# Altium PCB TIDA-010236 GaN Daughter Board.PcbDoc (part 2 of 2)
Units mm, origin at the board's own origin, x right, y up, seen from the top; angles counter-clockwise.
Board outline 68 x 45 mm, 4 copper layers (Top Layer, Signal Layer 1, Signal Layer 2, Bottom Layer), stack 1.57 mm thick; 74 components, 38 nets, 269 pads, 167 vias.
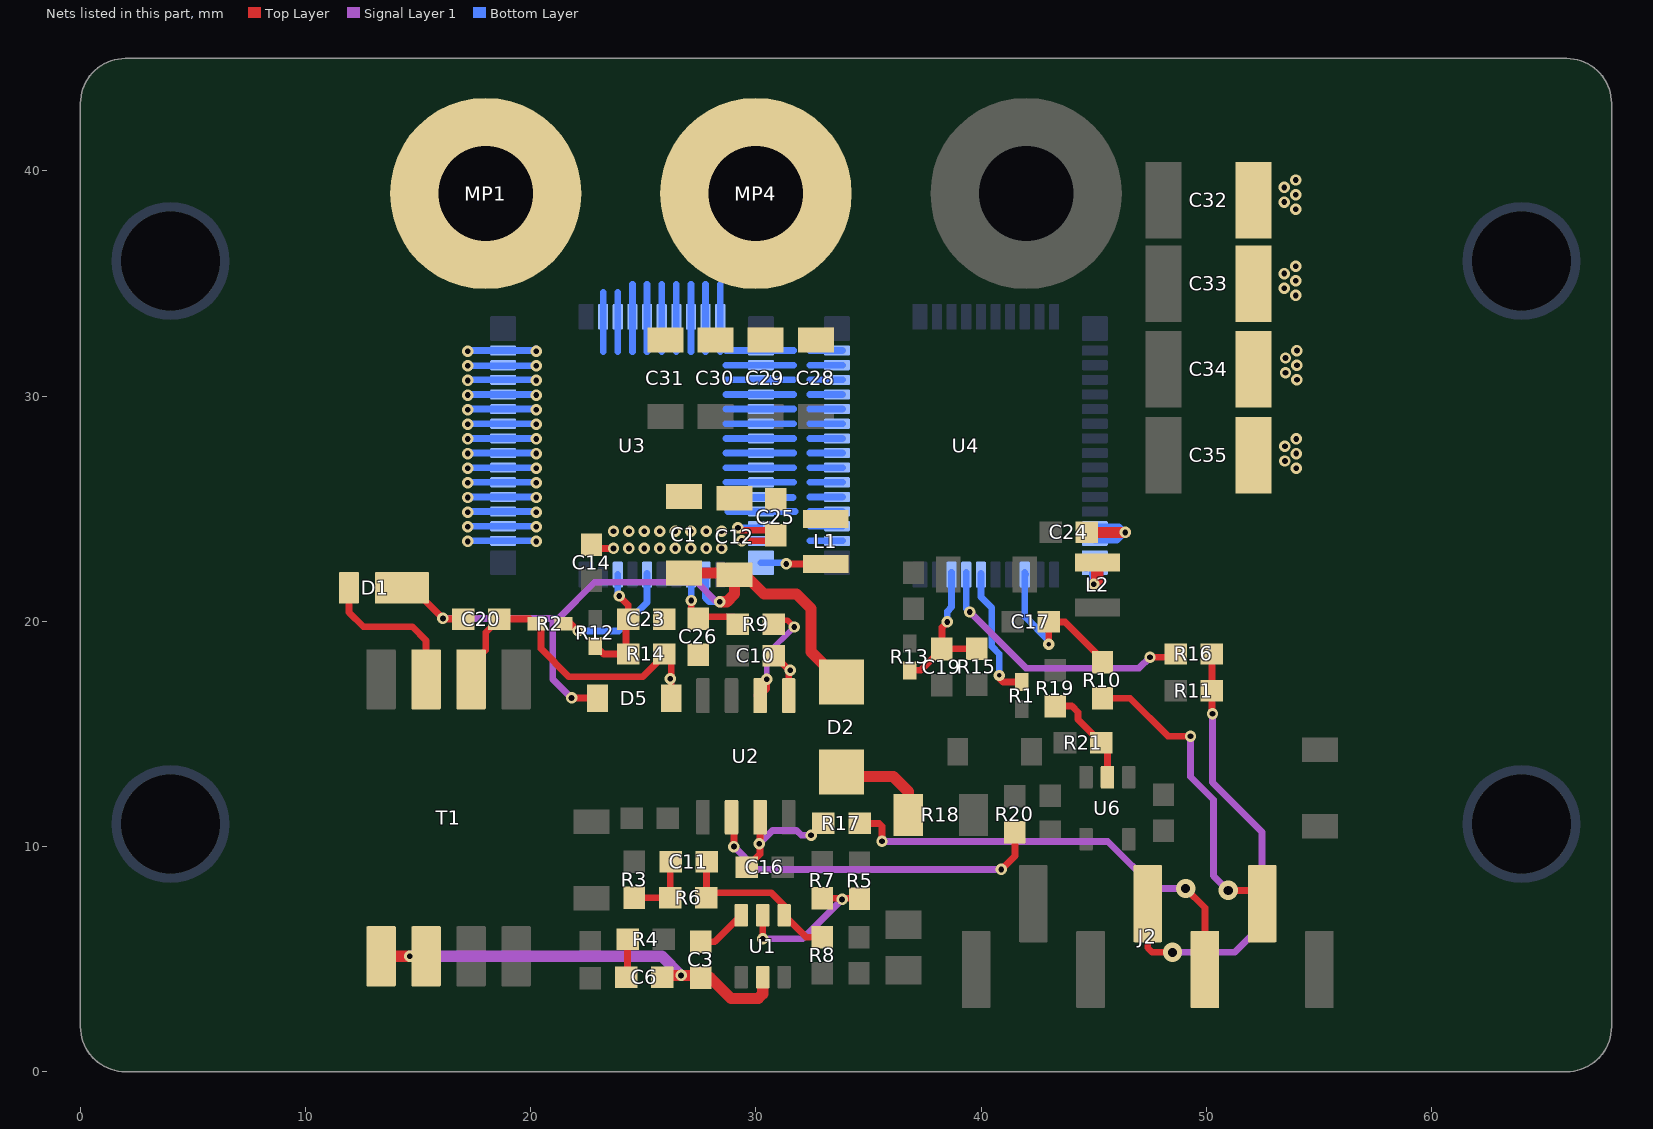
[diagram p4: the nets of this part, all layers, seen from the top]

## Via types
v1: diameter 0.508, hole 0.254, Top Layer to Bottom Layer, tented both sides, 150 vias
v2: diameter 0.5, hole 0.2, Top Layer to Bottom Layer, 12 vias
v3: diameter 0.864, hole 0.406, Top Layer to Bottom Layer, 5 vias

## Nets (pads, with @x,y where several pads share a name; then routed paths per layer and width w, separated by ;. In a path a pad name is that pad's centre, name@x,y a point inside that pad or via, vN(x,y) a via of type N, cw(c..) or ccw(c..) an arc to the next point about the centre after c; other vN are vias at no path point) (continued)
HV_BUS: C28.1 C29.1 C30.1 C31.1 C32.1 C33.1 C34.1 C35.1 MP1.1 U3.2 U3.3 U3.4 U3.5 U3.6 U3.7 U3.8 U3.9 U3.10 U3.11 U3.12 U3.13 U3.14 U3.15 | length 42.1
  Bottom Layer w0.3: v1(17.2,32) 17.225,32.025 U3.15@18.775,32.025 v1@20.225,32.025 ; v1@17.225,23.575 U3.2@18.775,23.575 v1@20.225,23.575 ; v1@17.225,24.225 U3.3@18.775,24.225 v1@20.225,24.225 ; v1@17.225,24.875 U3.4@18.775,24.875 v1@20.225,24.875 ; v1@17.225,25.525 U3.5@18.775,25.525 v1@20.225,25.525 ; v1@17.225,26.175 U3.6@18.775,26.175 v1@20.225,26.175 ; v1@17.225,26.825 U3.7@18.775,26.825 v1@20.225,26.825 ; v1@17.225,27.475 U3.8@18.775,27.475 v1@20.225,27.475 ; v1@17.225,28.125 U3.9@18.775,28.125 v1@20.225,28.125 ; v1@17.225,28.775 U3.10@18.775,28.775 v1@20.225,28.775 ; v1@17.225,29.425 U3.11@18.775,29.425 v1@20.225,29.425 ; v1@17.225,30.075 U3.12@18.775,30.075 v1@20.225,30.075 ; v1@17.225,30.725 U3.13@18.775,30.725 v1@20.225,30.725 ; v1@17.225,31.35 18.775,31.35 v1@20.225,31.35
  Bottom Layer w0.45: v1@20.225,32.025 v1(20.25,32)
  other v1: 17.2,23.55 20.25,23.55 17.2,24.2 20.25,24.2 17.2,24.85 20.25,24.85 17.2,25.5 20.25,25.5 17.2,26.15 20.25,26.15 17.2,26.8 20.25,26.8 54,26.8 53.492,27.12 17.2,27.45 20.25,27.45 54,27.45 53.492,27.77 17.2,28.1 20.25,28.1 54,28.1 17.2,28.75 20.25,28.75 17.2,29.4 20.25,29.4 17.2,30.05 20.25,30.05 17.2,30.7 20.25,30.7 54.025,30.725 53.517,31.045 17.2,31.35 20.25,31.35 54.025,31.375 53.517,31.695 54.025,32.025 53.975,34.475 53.467,34.795 53.975,35.125 53.467,35.445 53.975,35.775 53.975,38.3 53.467,38.62 53.975,38.95 53.467,39.27 53.975,39.6
ISO-15V: C1.1 C12.1 C20.1 D1.1 D2.1 D5.1 U3.44 | length 35.3
  Top Layer w0.3: D1.1@14.45,21.49 14.741,21.49 v1(16.1,20.131) 16.131,20.1 C20.1@17,20.1 ; v1(21.814,16.6) 22.915,16.6 22.801,16.714 22.812,16.725 D5.1@22.962,16.575 ; C1.1@26.8,22.15 C1.1@26.929,22.15
  Top Layer w0.5: C1.1@26.929,22.15 28.967,22.15 C12.1@29.05,22.067 ; v1(28.399,20.867) 28.705,20.867 29.05,21.212 C12.1@29.05,22.067 ; D2.1@33.8,17.3 32.45,18.65 32.45,20.569 31.804,21.216 30.366,21.216 29.515,22.067 C12.1@29.05,22.067
  Signal Layer 1 w0.3: v1(16.1,20.131) 20.975,20.131 ; v1(21.814,16.6) 20.975,17.439 20.975,20.131 ; v1(28.399,20.867) 28.258,20.867 27.389,21.736 22.836,21.736 21.231,20.131 20.975,20.131
  Bottom Layer w0.3: U3.44@27.765,22.075 27.765,21.044 27.942,20.867 v1(28.399,20.867)
NetC3_1: C3.1 C6.2 T1.1 T1.2 U1.2 | length 20.1
  Top Layer w0.5: T1.1@13.35,5.125 v1(14.625,5.125) T1.2@15.35,5.125 ; C6.2@25.85,4.2 25.925,4.275 v1(26.675,4.275) C3.1@27.55,4.275 ; C3.1@27.55,4.175 27.968,4.175 28.893,3.25 30.1,3.25 30.3,3.45 U1.2@30.3,4.2
  Signal Layer 1 w0.5: v1(14.625,5.125) 25.825,5.125 v1(26.675,4.275)
NetC3_2: C3.2 U1.6 | length 2.3
  Top Layer w0.3: C3.2@27.55,5.775 28.175,5.775 U1.6@29.35,6.95
NetC6_1: C6.1 R4.1 | length 1.7
  Top Layer w0.3: C6.1@24.25,4.2 24.3,4.25 R4.1@24.3,5.875
NetC11_1: C11.1 R3.1 R6.2 | length 3.2
  Top Layer w0.3: R3.1@24.594,7.725 R6.2@26.2,7.725 26.2,9.298 C11.1@26.225,9.323
NetC11_2: C11.2 R6.1 R8.2 U1.4 | length 7.9
  Top Layer w0.3: C11.2@27.825,9.323 27.8,9.298 R6.1@27.8,7.725 28.025,7.95 30.675,7.95 31.25,7.375 U1.4@31.25,6.95 32.225,5.975 R8.2@32.94,5.975
NetC16_1: C16.1 R17.2 U2.3 | length 5.9
  Top Layer w0.3: C16.1@29.6,9.075 30.185,9.66 U2.3@30.185,11.3 ; v1(32.45,10.5) 32.475,10.5 R17.2@33,11.025
  Signal Layer 1 w0.3: v1(30.15,10.125) 30.741,10.716 31.8,10.716 32.016,10.5 v1(32.45,10.5)
NetC17_1: C17.1 R10.1 U4.45 | length 8.2
  Top Layer w0.3: v2@43.064,19.041 v2(43,18.978) C17.1@43,19.974 43.735,19.974 45.484,18.225 R10.1@45.689,18.225
  Bottom Layer w0.3: U4.45@41.94,22.075 41.94,20.213 43,19.153 v2(43,18.978) ; U4.45@41.94,22.183 41.94,22.125 41.971,22.094 U4.45@41.971,22.075
NetC19_1: C19.1 R13.2 R15.2 U4.50 | length 7.2
  Top Layer w0.3: R13.2@36.825,17.825 37.313,17.825 C19.1@38.26,18.772 ; R13.2@36.85,17.84 R13.2@37.065,17.84 ; v1(38.5,19.974) 38.26,19.734 C19.1@38.26,18.772 ; R15.2@39.799,18.785 38.273,18.785 C19.1@38.26,18.772
  Bottom Layer w0.3: v1(38.5,19.974) 38.5,20.445 38.69,20.635 38.69,22.125 U4.50@38.69,22.183
NetC23_1: C23.1 R12.2 R14.2 U3.50 | length 5.6
  Top Layer w0.3: R12.2@22.875,18.9 23.225,18.55 R14.2@24.325,18.55 ; v1(23.925,21.125) 24.325,20.725 C23.1@24.325,20.1 24.225,20 24.225,18.725 R14.2@24.3,18.65 ; C23.1@24.001,19.926 C23.1@24.225,20.126
  Bottom Layer w0.3: U3.50@23.865,22.075 23.865,21.135 23.875,21.125 v1(23.925,21.125)
NetC24_1: C24.1 U4.40 U4.41 | length 5.2
  Top Layer w0.254: C24.1@44.7,23.95 C24.1@45.033,24.283
  Top Layer w0.5: C24.1@44.7,23.95 v1(46.403,23.95)
  Bottom Layer w0.254: U4.40@45,24.283 U4.40@45.058,24.225 ; U4.41@45.05,23.575 46.028,23.575 v1(46.403,23.95) 46.128,24.225 U4.40@45.058,24.225 ; U4.40@45.05,24.225 U4.40@45.058,24.225
NetC25_1: C25.1 U3.40 U3.41 | length 5.3
  Top Layer w0.3: v1(29.2,24.159) 29.309,24.05 30.608,24.05 30.885,23.773 30.638,23.525 30.588,23.575 v1(29.375,23.575)
  Bottom Layer w0.3: v1(29.2,24.159) 30.109,24.159 U3.40@30.175,24.225 ; v1(29.375,23.575) U3.41@30.175,23.575
NetC26_1: C26.1 R9.1 U3.45 | length 3.4
  Top Layer w0.3: v1(27.125,20.925) 27.125,20.441 27.425,20.141 C26.1@27.46,20.176 ; C26.1@27.65,20.209 R9.1@28.984,20.209
  Bottom Layer w0.3: U3.45@27.115,22.075 27.125,22.065 v1(27.125,20.925)
NetD1_2: D1.2 T1.7 | length 6.8
  Top Layer w0.3: D1.2@11.925,21.49 11.925,20.4 12.562,19.763 14.737,19.763 15.35,19.15 T1.7@15.35,17.425
NetD2_2: D2.2 R18.2 | length 4.4
  Top Layer w0.5: D2.2@33.8,13.3 33.986,13.114 36.1,13.114 36.765,12.448 R18.2@36.765,11.4
NetL1_2: L1.2 U3.42 | length 2.9
  Top Layer w0.3: v1(31.35,22.55) L1.2@33.1,22.55
  Bottom Layer w0.3: U3.42@30.225,22.6 31.3,22.6 v1(31.35,22.55)
NetL2_2: L2.2 U4.42 | length 3.9
  Top Layer w0.254: v1(45.004,21.647) 45.004,22.286 44.925,22.365 L2.2@45.175,22.615
  Top Layer w0.5: v1(45.004,21.647) 45.175,21.818 L2.2@45.175,22.615
  Bottom Layer w0.254: U4.42@44.65,22.308 U4.42@45,22.658 ; v1(45.004,21.647) 45.004,21.954
  Bottom Layer w0.5: v1(45.004,21.647) 45.05,21.693 U4.42@45.05,22.6
NetR1_2: R1.2 U4.48 | length 6.1
  Top Layer w0.3: v2(40.807,17.6) 40.807,17.469 40.976,17.301 R1.2@41.8,17.301
  Bottom Layer w0.3: U4.48@39.99,22.125 U4.48@39.99,22.075 39.99,21.086 40.476,20.6 40.476,18.885 40.807,18.554 v2(40.807,17.6)
NetR2_2: R2.2 U3.48 | length 5.8
  Top Layer w0.3: R2.2@21.35,19.9 21.775,19.9 v1(22.1,19.575)
  Bottom Layer w0.3: v1(22.1,19.575) 23.904,19.575 25.165,20.836 U3.48@25.165,22.125
NetR5_1: R5.1 R7.2 U1.5 | length 7
  Top Layer w0.3: v1(30.3,5.909) U1.5@30.3,6.95 ; R7.2@32.94,7.7 34.575,7.7 R5.1@34.6,7.675
  Signal Layer 1 w0.3: v1(30.3,5.909) 32.084,5.909 v1(33.825,7.65)
NetR16_2: R16.2 U4.49 | length 13.1
  Top Layer w0.3: v1(47.5,18.4) 48.5,18.4 R16.2@48.65,18.55
  Signal Layer 1 w0.3: v1(39.5,20.415) 41.995,17.92 47.02,17.92 v1(47.5,18.4)
  Bottom Layer w0.3: 39.34,21.26 U4.49@39.34,22.183 ; U4.49@39.34,22.075 39.34,20.575 v1(39.5,20.415)
NetR19_2: R19.2 R21.2 U6.2 | length 4.6
  Top Layer w0.3: R19.2@43.246,16.434 R19.2@43.293,16.434 ; R19.2@43.293,16.235 44.028,16.235 44.3,15.963 44.3,15.639 R21.2@45.326,14.613 45.611,14.328 U6.2@45.611,13.075
NetR20_1: R20.1 U2.2 | length 15.6
  Top Layer w0.3: U2.2@28.915,11.3 28.82,11.205 29.021,11.003 v1(29.021,9.999) ; v1(40.9,8.984) 41.5,9.584 R20.1@41.5,10.628
  Signal Layer 1 w0.3: v1(29.021,9.999) 30.036,8.984 v1(40.9,8.984)
PWM_H: J2.3 R17.1 | length 20
  Top Layer w0.3: R17.1@34.6,11.025 35.475,11.025 35.6,10.9 v1(35.6,10.228) ; v3(49.084,8.135) 49.94,7.279 J2.3@49.94,4.54
  Signal Layer 1 w0.3: v1(35.6,10.228) 45.623,10.228 47.715,8.135 v3(49.084,8.135)
PWM_HS: R9.2 U2.6 | length 4.8
  Top Layer w0.254: R9.2@30.825,20.05 31.4,20.05 v1(31.7,19.75)
  Top Layer w0.3: U2.6@30.05,16.7 U2.6@30.185,16.7 30.475,16.99 v1(30.475,17.425)
  Signal Layer 1 w0.254: v1(30.475,17.425) 30.475,18.525 v1(31.7,19.75)
PWM_L: J2.2 R10.2 | length 13.9
  Top Layer w0.3: R10.2@45.389,16.585 46.615,16.585 48.3,14.9 v1(49.3,14.9) ; R10.2@45.457,16.981 R10.2@45.623,16.816 ; v3(50.974,8.049) 52.339,8.049 J2.2@52.46,8.17
  Signal Layer 1 w0.3: v1(49.3,14.9) 49.3,13.1 50.324,12.076 50.324,8.699 v3(50.974,8.049)
SW: C1.2 C10.2 C12.2 C14.1 C20.2 C23.2 C25.2 C26.2 D5.2 L1.1 MP4.1 R2.1 R14.1 T1.6 U2.5 U3.18 U3.19 U3.20 U3.21 U3.22 U3.23 U3.24 U3.25 U3.26 U3.28 U3.29 U3.30 U3.31 U3.32 U3.33 U3.34 U3.35 U3.36 U3.37 U3.38 U3.39 U4.2 U4.3 U4.4 U4.5 U4.6 U4.7 U4.8 U4.9 U4.10 U4.11 U4.12 U4.13 U4.14 U4.15 | length 100.7
  Top Layer w0.3: T1.6@17.35,17.425 17.35,18.075 18,18.725 18,19.5 C20.2@18.6,20.1 19.95,20.1 20.45,19.6 20.45,18.785 21.7,17.535 24.968,17.535 R14.1@25.991,18.559 ; C14.1@22.7,23.4 22.862,23.238 v1(23.674,23.238) ; R14.1@25.825,18.725 R14.1@25.991,18.559 ; D5.2@26.237,16.575 26.237,18.313 R14.1@25.991,18.559 ; C1.2@26.8,25.45 C1.2@26.877,25.373 ; C10.2@30.8,18.525 31.455,17.87 U2.5@31.455,16.7
  Bottom Layer w0.3: 23.215,31.975 U3.18@23.215,33.525 23.215,34.6 ; 23.865,31.975 U3.19@23.865,33.525 23.865,34.6 ; 24.515,31.975 U3.20@24.515,33.525 24.515,34.975 ; 25.165,31.975 U3.21@25.165,33.525 25.165,34.975 ; 25.815,31.975 U3.22@25.815,33.525 25.815,34.975 ; 26.465,31.975 U3.23@26.465,33.525 26.465,34.975 ; 27.115,31.975 U3.24@27.115,33.525 27.115,34.975 ; 27.765,31.975 U3.25@27.765,33.525 27.765,34.975 ; 28.415,31.975 U3.26@28.415,33.525 28.415,34.975 ; 28.65,25.5 31.65,25.5 ; 28.675,26.175 U3.37@30.225,26.175 31.675,26.175 ; 28.675,26.825 U3.36@30.225,26.825 31.675,26.825 ; 28.675,27.475 U3.35@30.225,27.475 31.675,27.475 ; 28.675,28.125 U3.34@30.225,28.125 31.675,28.125 ; 28.675,28.775 U3.33@30.225,28.775 31.675,28.775 ; 28.675,29.425 U3.32@30.225,29.425 31.675,29.425 ; 28.675,30.075 U3.31@30.225,30.075 31.675,30.075 ; 28.675,30.725 U3.30@30.225,30.725 31.675,30.725 ; 28.675,31.375 U3.29@30.225,31.375 31.675,31.375 ; 28.675,32.025 U3.28@30.225,32.025 31.675,32.025 ; 28.75,24.875 31.75,24.875 ; 32.395,23.575 U4.2@33.845,23.575 ; 32.395,24.225 U4.3@33.845,24.225 ; 32.395,24.875 U4.4@33.845,24.875 ; 32.395,25.525 U4.5@33.845,25.525 ; 32.395,26.175 U4.6@33.845,26.175 ; 32.395,26.825 U4.7@33.845,26.825 ; 32.395,27.475 U4.8@33.845,27.475 ; 32.395,28.125 U4.9@33.845,28.125 ; 32.395,28.775 U4.10@33.845,28.775 ; 32.395,29.425 U4.11@33.845,29.425 ; 32.395,30.075 U4.12@33.845,30.075 ; 32.395,30.725 U4.13@33.845,30.725 ; 32.395,31.375 U4.14@33.845,31.375 ; 32.395,32.025 U4.15@33.845,32.025
  other v1: 26.2,17.45 31.524,17.834 24.36,23.238 25.046,23.238 25.732,23.238 26.418,23.238 27.103,23.238 27.789,23.238 28.475,23.238 23.674,24 24.36,24 25.046,24 25.732,24 26.418,24 27.103,24 27.789,24 28.475,24
TEMP_L: J2.4 R11.1 R16.1 | length 21.8
  Top Layer w0.3: J2.4@47.4,8.65 J2.4@47.4,7.46 47.4,5.5 47.6,5.3 v3(48.5,5.3) ; R16.1@50.25,18.55 R11.1@50.25,16.925 50.25,15.925 v1(50.275,15.9)
  Signal Layer 1 w0.3: v3(48.5,5.3) 51.25,5.3 52.475,6.525 52.475,10.65 50.275,12.85 v1(50.275,15.9)
pads on no net: MP3. MP3.1 MP6. MP6.1 MP8. MP8.1 MP9. MP9.1 T1.5 T1.8 U3.1 U3.16 U3.17 U3.27 U3.43 U3.47 U3.49 U3.52 U4.1 U4.16 U4.17 U4.27 U4.43 U4.47 U4.52

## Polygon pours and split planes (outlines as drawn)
GND on Bottom Layer "Bottom Layer-GND" (solid, pour order 144): 37,29.425 37,23.1 37.175,22.925 42.949,22.925 43.4,23.376 43.4,24 44.073,24.673 44.073,33.373 44.6,33.9 45.9,33.9 46,33.8 46,24.936 46.3,24.636 48.536,24.636 48.9,25 48.9,40.75 46.65,43 37.6,43 37,42.4 37,35.4 37.8,34.6 43.424,34.6 43.7,34.324 43.7,32.699 43.499,32.5 37.507,32.5 37.007,32
HV_BUS on Bottom Layer "Bottom Layer-HV_BUS" (solid, pour order 134): 13,24.3 14.025,23.275 17.1,23.275 17.5,23.675 17.5,33.7 17.8,34 19.5,34 19.8,33.7 19.8,23.5 20.025,23.275 20.475,23.275 20.7,23.5 20.7,35.3 22.5,37.1 22.5,41.75 21.25,43 14,43 13,42
SW on Bottom Layer "Bottom Layer-SW" (solid, pour order 132): 22.7,23.4 23.2,22.9 28.809,22.9 29,23.091 29,24.436 29.375,24.811 29.375,33.475 29.7,33.8 30.8,33.8 31.1,33.5 31.1,23.483 31.232,23.351 32.601,23.351 32.8,23.55 32.8,33.686 34.6,35.486 34.6,41.5 33.1,43 26.7,43 25.7,42 25.7,37.5 23.086,34.886 23,34.8 23,34.386 23.1,34.286 28.564,34.286 28.809,34.041 28.809,32.609 28.7,32.5 22.907,32.5 22.7,32.293
HV_BUS on Bottom Layer "BOTTOM_LAYER_HV_BUS_P046" (solid, remove dead copper, pour order 46): 51,25.7 51,40.275 51.2,40.475 54.133,40.475 54.725,39.883 54.725,26.4 53.988,25.663
GND on Signal Layer 1 "Signal Layer 1-GND" (solid, pour order 114): 48.175,34.125 48.9,34.85 48.9,40.75 48.298,41.353 46.65,43 39.675,43 38,41.325 38,35.748 39.623,34.125
HV_BUS on Signal Layer 1 "Signal Layer 1-HV_BUS" (solid, pour order 112): 21.612,26.387 33.065,26.387 33.814,25.638 54.287,25.638 54.287,39.837 53.65,40.475 51.2,40.475 51,40.275 51,34.5 50.062,33.562 25.004,33.563 21.9,36.667 21.9,41.721 20.605,43.016 14.897,43.016 13.8,41.919 13.8,41 13.8,25.775 17.263,22.313 20.538,22.313 20.863,22.638 20.863,25.638
GND on Signal Layer 2 "Signal Layer 2-GND" (solid, pour order 108): 48.55,34.5 48.9,34.85 48.9,40.75 48.298,41.353 46.65,43 39.675,43 37.631,40.956 37.631,36.117 39.248,34.5
HV_BUS on Signal Layer 2 "Signal Layer 2-HV_BUS" (solid, pour order 102): 13,26.5 17.22,22.28 19.888,22.28 23.309,25.7 54.225,25.7 54.225,39.883 53.633,40.475 51,40.475 51,34.5 49.975,33.475 25.086,33.475 21.9,36.661 21.9,41.732 20.616,43.016 14.016,43.016 13,42
GND on Signal Layer 2 "SIGNAL_LAYER_2_GND_P038" (solid, remove dead copper, pour order 38): 36.85,24.425 42.275,24.425 45.105,21.595 54.705,21.595 56.525,19.775 56.525,3.25 56,2.725 11.8,2.725 10.975,3.55 10.975,10.25 12.775,12.05 35.85,12.05 36.85,13.05
SW on Signal Layer 2 "SIGNAL_LAYER_2_SW_P034" (solid, remove dead copper, pour order 34): 22.2,16.4 22.2,23.1 23.5,24.4 29.864,24.4 31.95,22.314 31.95,15.975 22.625,15.975
SW on Top Layer "Top Layer-SW" (solid, pour order 122): 25.1,20.755 25.1,18.3 25.625,17.775 28,17.775 28.35,18.125 28.35,23.5 33.815,23.5 34.15,23.835 34.15,25.061 33.017,26.195 32.405,26.195 32.4,26.2 32.394,26.195 24.82,26.195 22.6,23.975 22.6,23.255
GND on Top Layer "Top Layer-GND" (solid, pour order 94): 48.425,24.925 48.9,25.4 48.9,40.75 46.65,43 39.675,43 38.007,41.332 38.007,32.557 35.125,29.675 25.225,29.675 25,29.5 25,28.725 25.2,28.525 34.15,28.525 37,25.675 37,25.658 37.733,24.925
HV_BUS on Top Layer "Top Layer-HV_BUS" (solid, pour order 90): 23.3,31.925 33.682,31.925 33.907,32.15 33.907,33.068 33.793,33.182 25.368,33.182 22.425,36.125 22.425,41.187 20.596,43.016 14.897,43.016 13,41.119 13,26.45 17.17,22.28 20.515,22.28 20.515,25.74 22.425,27.65 22.425,31.05
GND on Top Layer "TOP_LAYER_GND_P014" (solid, remove dead copper, pour order 14): 36.55,21.605 36.55,24.072 37.226,24.749 43.336,24.749 43.6,24.484 43.6,23.052 42.398,23.052 40.752,23.052 40.752,21.587
HV_BUS on Top Layer "TOP_LAYER_HV_BUS_P010" (solid, remove dead copper, pour order 10): 51.278,25.68 51.278,40.475 54.15,40.475 54.75,39.875 54.75,33.318 54.75,26.425 54.005,25.68

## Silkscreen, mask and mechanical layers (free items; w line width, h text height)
Top Overlay:
  text "SW" at 25.165,33.525 h1.85
  text "HV" at 17.017,32.699 h1.85
  text "GND" at 39.99,32.7 h1.85
  text "TIDA-010236" at 0.431,27.65 h2.75
  text "GaN Daughter" at 0.476,25.525 h2.75
  text "Board" at 4,23.4 h2.75
  text "20221214" at 0.365,21.076 h2.75
  text "Rev. B" at 2.39,19.053 h2.75
  text "PL" at 53,3.4 h0.55 r90
  text "PH" at 51.47,3.3 h0.55 r90
  text "15V" at 41.279,2.8 h0.55 r90
  text "GND" at 43.246,2.8 h0.55 r90
  text "FLT" at 46.3,2.8 h0.55 r90
  text "TMP" at 47.745,2.7 h0.55 r90
  text "3.3V" at 56.6,2.476 h0.55 r90
M1 Board Outline:
  lines w0.254: 1.984,45 66,45 cw(c66,43) 68,43 68,4 68,2 cw(c66,2) 66,0 2,0 cw(c2,2) 0,2 0,4 0,43 cw(c2,43) 2,45
M2 Board Dimensions:
  circle w0.254: c24.993,6.025 r1
  circle w0.254: c22.453,6 r1
  circle w0.254: c19.913,6 r1
  circle w0.254: c17.373,6 r1
  circle w0.254: c14.833,6 r1
  circle w0.254: c12.293,6 r1
  circle w0.254: c9.753,6 r1
  text ".Layer_Name" at -5.344,-19.806 h1.52
M4 3D STEP Bottom:
  text ".Layer_Name" at -5.344,-19.806 h1.52
M5 Assembly Top:
  lines w0.254: -27.417,-21.626 140.223,-21.626 ; -27.417,-16.462 140.274,-16.462 ; -27.417,-11.297 -27.417,-26.791 74.31,-26.791 140.274,-26.791 140.274,-11.297 -27.404,-11.297 -27.404,-26.791 12.614,-26.791 ; 35.194,-26.791 35.194,-11.297 ; 67.376,-16.462 67.376,-11.297 ; 88.712,-16.462 88.712,-11.297 ; 104.511,-26.956 104.511,-21.804
  text "COMPONENTS MARKED 'DNP' SHOULD NOT BE POPULATED." at 9.299,-6.09 h1.52
  text "ASSEMBLY VARIANT:" at 9.286,-9.024 h1.52
  text ".VariantName" at 35.601,-9.024 h1.52
  text "PCB VIEWED FROM TOP SIDE" at -25.804,-14.654 h1.52
  text "BOARD #:" at 37.099,-14.654 h1.52
  text ".PRJ_Number" at 50.955,-14.654 h1.52
  text "REV:" at 72.405,-14.654 h1.52
  text ".PCB_Rev" at 79.809,-14.654 h1.52
  text "SVN REV:" at 93.69,-14.654 h1.52
  text ".VersionControl_RevNumber" at 106.543,-14.654 h1.52
  text "TID #:" at 37.099,-19.819 h1.52
  text ".TID" at 50.955,-19.819 h1.52
  text "PLOT NAME =" at -25.804,-25.034 h1.52
  text ".plot_File_Name" at -5.344,-25.034 h1.52
  text "GENERATED    :" at 37.15,-25.034 h1.52
  text ".Print_Date" at 59.235,-25.034 h1.52
  text ".Print_Time" at 77.752,-25.034 h1.52
  text "TEXAS INSTRUMENTS" at 109.87,-25.034 h1.52
M6 Assembly Bottom:
  lines w0.254: -27.43,-16.474 140.261,-16.474 ; -27.379,-21.639 140.261,-21.639 ; 8.334,-26.969 8.334,-21.817 ; 24.132,-16.474 24.132,-11.31 ; 45.468,-16.474 45.468,-11.31 ; 77.65,-26.804 77.65,-11.31 ; 100.231,-26.804 140.249,-26.804 140.249,-11.31 -27.43,-11.31 -27.43,-26.804 38.534,-26.804 140.261,-26.804 140.261,-11.31
  text "COMPONENTS MARKED 'DNP' SHOULD NOT BE POPULATED." at 134.991,-6.077 h1.52
  text ".VariantName" at 108.473,-9.024 h1.52
  text "ASSEMBLY VARIANT:" at 134.864,-9.024 h1.52
  text ".VersionControl_RevNumber" at 6.302,-14.667 h1.52
  text "SVN REV:" at 19.154,-14.667 h1.52
  text ".PCB_Rev" at 33.035,-14.667 h1.52
  text "REV:" at 40.439,-14.667 h1.52
  text ".PRJ_Number" at 61.89,-14.667 h1.52
  text "BOARD #:" at 75.745,-14.667 h1.52
  text "PCB VIEWED FROM BOTTOM SIDE" at 138.648,-14.667 h1.52
  text ".TID" at 61.89,-19.831 h1.52
  text "TID #:" at 75.745,-19.831 h1.52
  text "TEXAS INSTRUMENTS" at 2.974,-25.047 h1.52
  text ".Print_Time" at 35.093,-25.047 h1.52
  text ".Print_Date" at 53.609,-25.047 h1.52
  text "GENERATED    :" at 75.694,-25.047 h1.52
  text ".plot_File_Name" at 118.189,-25.047 h1.52
  text "PLOT NAME =" at 138.648,-25.047 h1.52
M9 Title Sheet:
  drawing of 57 lines, arcs and shapes, not listed
  text "1" at -1.208,206.127 h1.78
  text "2" at 62.182,206.127 h1.78
  text "3" at 125.411,206.127 h1.78
  text "4" at 189.08,206.127 h1.78
  text "5" at 252.555,206.127 h1.78
  text "6" at 316.182,206.127 h1.78
  text "A" at -30.579,177.095 h1.78
  text "A" at 345.341,177.095 h1.78
  text "B" at -30.579,116.643 h1.78
  text "B" at 345.341,116.643 h1.78
  text "C" at -30.579,56.318 h1.78
  text "C" at 345.341,56.318 h1.78
  text "PROJECT TITLE:" at 268.125,9.049 h1.14
  text ".PRJ_Title" at 269.395,5.662 h1.78
  text "DESIGNED FOR:" at 268.125,1.403 h1.14
  text ".PRJ_Customer" at 269.395,-2.153 h1.78
  text "D" at -30.579,-3.88 h1.78
  text "D" at 345.341,-3.88 h1.78
  text "FILE NAME:" at 268.125,-6.217 h1.14
  text ".PCB_File_Name_No_Path" at 269.395,-9.265 h1.78
  text "Texas Instruments (TI) and/or its licensors do not warrant the accuracy or completeness of this specification" at 141.9,-13.376 h1.14
  text "ENGINEER:" at 268.125,-13.583 h1.14
  text "LAYOUT BY:" at 306.352,-13.583 h1.14
  text "or any information contained therein. TI and/or its licensors do not warrant that this design will meet" at 140.757,-16.237 h1.14
  text ".PRJ_Engineer" at 269.395,-17.52 h1.78
  text ".PCB_Layout" at 307.635,-17.52 h1.78
  text "the specifications, will be suitable for your application or fit for any particular purpose, or will operate in" at 140.757,-19.099 h1.14
  text ".Layer_Name" at -5.344,-19.806 h1.52
  text "ALTIUM DESIGNER VERSION:" at 306.352,-21.457 h1.14
  text "an implementation. TI and/or its licensors do not warrant that the design is production worthy. You should" at 140.757,-21.961 h1.14
  text "completely validate and test your design implementation to confirm the system functionality for your application." at 141.9,-24.822 h1.14
  text ".print_Scale" at 269.395,-24.843 h1.78
  text ".Application_BuildNumber" at 307.635,-24.843 h1.78
  text "1" at -1.208,-30.093 h1.78
  text "2" at 62.182,-30.093 h1.78
  text "3" at 125.411,-30.093 h1.78
  text "4" at 189.08,-30.093 h1.78
  text "5" at 252.555,-30.093 h1.78
  text "6" at 316.182,-30.093 h1.78
M10 Fab Notes:
  drawing of 189 lines, arcs and shapes, not listed
  text "DESIGN INFORMATION" at 294.503,163.447 h1.52
  text "MIN. TRACK WIDTH:" at 278.131,160.091 h1.52
  text "8" at 305.976,160.091 h1.52
  text "MIL" at 309.907,160.091 h1.52
  text "MIN. CLEARANCE:" at 278.131,156.938 h1.52
  text "0.2" at 304.452,156.938 h1.52
  text "mm" at 309.907,156.938 h1.52
  text "MIN. VIA PAD SIZE:" at 278.131,153.785 h1.52
  text "24" at 305.214,153.785 h1.52
  text "MIL" at 309.907,153.785 h1.52
  text "0.05mm (2MIL)" at 295.784,150.486 h1.52
  text "MINIMUM ANNULAR RING" at 269.769,150.277 h1.52
  text "EXTERNAL" at 313.768,150.277 h1.52
  text "PER" at 274.849,147.48 h1.52
  text "IPC-D-275 CLASS 2 LEVEL C" at 280.437,147.48 h1.52
  text "MIL, HOLES" at 318.238,144.928 h1.52
  text "+/-" at 308.27,144.709 h1.52
  text "+/-" at 329.961,144.709 h1.52
  text "REGISTRATION TOLERANCES:" at 269.769,144.682 h1.52
  text "METAL" at 300.243,144.682 h1.52
  text "5" at 314.879,144.683 h1.52
  text "3" at 336.037,144.683 h1.52
  text "MIL" at 338.99,144.682 h1.52
  text "HOLE SIZE TOLERANCE (UNLESS OTHERWISE SPECIFIED):" at 269.769,142.185 h1.52
  text "+/-" at 329.961,142.112 h1.52
  text "3" at 336.037,142.085 h1.52
  text "MIL" at 338.99,142.085 h1.52
  text "MATERIAL:" at 267.87,138.589 h1.52
  text "FR-4 High Tg" at 292.926,135.324 h1.52
  text "X" at 289.257,135.122 h1.52
  text "FR-408" at 278.563,135.007 h1.52
  text "OTHER" at 316.358,135.007 h1.52
  text "62 MIL (1.6mm) +/-10%" at 286.694,131.374 h1.52
  text "X" at 283.643,131.312 h1.52
  text "THICKNESS:" at 269.769,131.165 h1.52
  text "OTHER" at 319.33,131.165 h1.52
  text "TOLERANCE:" at 269.769,127.652 h1.52
  text "X" at 291.314,127.652 h1.52
  text "ANSI IPC-6012 TYPE 3 CLASS 2" at 295.836,127.652 h1.52
  text "OTHER +/-" at 295.835,123.989 h1.52
  text "BOW & TWIST:" at 269.769,120.302 h1.52
  text "X" at 291.314,120.302 h1.52
  text "ANSI IPC-6012 TYPE 3 CLASS 2" at 295.836,120.302 h1.52
  text "OTHER +/-" at 295.835,116.576 h1.52
  text "DRILLING:" at 267.87,113.258 h1.52
  text "NC_DRILL FILES" at 312.599,110.586 h1.52
  text "REFERENCE:" at 269.769,110.486 h1.52
  text "X" at 286.463,110.484 h1.52
  text "AS SHOWN" at 290.984,110.486 h1.52
  text "X" at 309.348,110.486 h1.52
  text "OTHER" at 320.168,106.873 h1.52
  text "PTH COPPER THICKNESS:" at 269.761,106.783 h1.52
  text "X" at 298.697,106.783 h1.52
  text "20-30 um" at 301.948,106.783 h1.52
  text "BOARD FINISH:" at 267.87,103.034 h1.52
  text "SILKSCREEN:" at 271.812,100.237 h1.52
  text "X" at 296.14,100.237 h1.52
  text "TOP" at 299.112,100.237 h1.52
  text "X" at 309.094,100.237 h1.52
  text "BOTTOM" at 312.091,100.237 h1.52
  text "SILKSCREEN COLOR:" at 271.812,96.295 h1.52
  text "X" at 296.115,96.295 h1.52
  text "WHITE" at 299.112,96.295 h1.52
  text "OTHER" at 312.091,96.295 h1.52
  text "X" at 299.442,92.652 h1.52
  text "GREEN" at 302.439,92.652 h1.52
  text "OTHER" at 318.136,92.652 h1.52
  text "SOLDER RESIST COLOR:" at 271.812,92.477 h1.52
  text "X" at 299.442,88.734 h1.52
  text "MATTE" at 302.439,88.734 h1.52
  text "SEMI-GLOSS" at 318.125,88.717 h1.52
  text "IMMERSION GOLD (ENIG)" at 294.819,84.345 h1.52
  text "ENEPIG" at 328.793,84.162 h1.52
  text "SURFACE FINISH:" at 267.87,84.136 h1.52
  text "X" at 290.298,84.136 h1.52
  text "IMM. TIN/SILVER OR EQUIV" at 276.24,80.649 h1.52
  text "OTHER" at 312.599,80.549 h1.52
  text "ARRAY/PANEL:" at 267.87,76.602 h1.52
  text "CUT AND TRIM PER M1 BOARD OUTLINE" at 294.819,76.393 h1.52
  text "N.C. ROUTE" at 294.819,72.94 h1.52
  text "X" at 312.295,72.94 h1.52
  text "V. SCORE" at 316.816,72.94 h1.52
  text "CERTIFICATION:" at 267.87,69.66 h1.52
  text "MATERIALS AND WORKMANSHIP FOR ALL PCBS" at 286.285,69.66 h1.52
  text "TO MEET OR EXCEED THE REQUIREMENTS OF:" at 286.285,67.271 h1.52
  text "X" at 277.078,64.003 h1.52
  text "ANSI IPC-A-600F CLASS ->" at 280.329,64.003 h1.52
  text "X" at 322.188,64.003 h1.52
  text "2" at 324.982,64.003 h1.52
  text "1" at 316.981,63.965 h1.52
  text "3" at 333.973,63.965 h1.52
  text "X" at 297.702,60.252 h1.52
  text "RoHS" at 300.953,60.252 h1.52
  text "OTHER" at 317.321,60.252 h1.52
  text "PER ORDER" at 327.407,60.252 h1.52
  text "ALL BOARDS MUST MEET OR EXCEED UL94-V0 REQUIREMENTS." at 268.569,56.345 h1.52
  text "PCB MUST BEAR THE UL94V-0 UL REGISTERED MATERIAL ID NUMBER" at 268.569,53.397 h1.52
  text "ADDITIONAL REQUIREMENTS:" at 267.87,49.094 h1.52
  text "MICROSECTION:" at 269.769,46.373 h1.52
  text "YES" at 292.775,46.373 h1.52
  text "REQUIRED" at 314.657,42.707 h1.52
  text "BARE BOARD ELEC. TEST:" at 269.769,42.634 h1.52
  text "NONE" at 302.935,42.634 h1.52
  text "X" at 311.66,42.634 h1.52
  text "PER ORDER" at 329.693,42.634 h1.52
  text "XX MIL VIAS REQUIRE NON-CONDUCTIVE FILL AND PLANARIZE" at 274.04,37.428 h1.5
  text "XX MIL VIAS REQUIRE CONDUCTIVE FILL AND PLANARIZE" at 274.243,34.787 h1.52
  text "OUTER XX MIL TRACES REQUIRE 50 OHM SINGLE-ENDED IMPEDANCE" at 274.218,30.637 h1.47
  text "LAYER 2 & 3 (INNER LAYERS) XX MIL WIDE, XX MIL SPACE / TRACES REQUIRE 100 OHM DIFFERENTIAL IMPEDANCE" at 274.015,24.65 h1.52
  text ".Layer_Name" at -5.344,-19.806 h1.52
M11 Gerber Information:
  lines w0.254: -27.417,-21.626 140.223,-21.626 ; -27.417,-16.462 140.274,-16.462 ; -27.417,-11.297 -27.417,-26.791 74.31,-26.791 140.274,-26.791 140.274,-11.297 -27.404,-11.297 -27.404,-26.791 12.614,-26.791 ; 35.194,-26.791 35.194,-11.297 ; 67.376,-16.462 67.376,-11.297 ; 88.712,-16.462 88.712,-11.297 ; 104.511,-26.956 104.511,-21.804
  text "ALL ARTWORK VIEWED FROM TOP SIDE" at -25.804,-14.654 h1.52
  text "BOARD #:" at 37.099,-14.654 h1.52
  text ".PRJ_Number" at 50.955,-14.654 h1.52
  text "REV:" at 72.405,-14.654 h1.52
  text ".PCB_Rev" at 79.809,-14.654 h1.52
  text "SVN REV:" at 93.69,-14.654 h1.52
  text ".VersionControl_RevNumber" at 106.543,-14.654 h1.52
  text "LAYER NAME =" at -25.804,-19.806 h1.52
  text "TID #:" at 37.099,-19.819 h1.52
  text ".TID" at 50.955,-19.819 h1.52
  text "PLOT NAME =" at -25.804,-25.034 h1.52
  text ".plot_File_Name" at -5.344,-25.034 h1.52
  text "GENERATED    :" at 37.15,-25.034 h1.52
  text ".Print_Date" at 59.235,-25.034 h1.52
  text ".Print_Time" at 77.752,-25.034 h1.52
  text "TEXAS INSTRUMENTS" at 109.87,-25.034 h1.52
M12 Stackup:
  drawing of 295 lines, arcs and shapes, not listed
  text "Layer" at 102.33,137.55 h1.52
  text "Name" at 112.742,137.55 h1.52
  text "Material" at 136.612,137.55 h1.52
  text "Thickness" at 158.45,137.55 h1.52
  text "Constant" at 174.956,137.55 h1.52
  text "Board Layer Stack" at 189.43,137.55 h1.52
  text "Top Overlay" at 112.742,134.502 h1.52
  text "Top Solder" at 112.742,131.454 h1.52
  text "Solder Resist" at 136.612,131.454 h1.52
  text "0.010mm" at 158.45,131.454 h1.52
  text "3.5" at 174.956,131.454 h1.52
  text "1" at 102.33,128.406 h1.52
  text "Top Layer" at 112.742,128.406 h1.52
  text "0.070mm" at 158.45,128.406 h1.52
  text "Dielectric 2" at 112.742,125.358 h1.52
  text "0.430mm" at 158.45,125.358 h1.52
  text "4.2" at 174.956,125.358 h1.52
  text "2" at 102.33,122.31 h1.52
  text "Signal Layer 1" at 112.742,122.31 h1.52
  text "0.070mm" at 158.45,122.31 h1.52
  text "Dielectric 3" at 112.742,119.262 h1.52
  text "0.430mm" at 158.45,119.262 h1.52
  text "4.2" at 174.956,119.262 h1.52
  text "3" at 102.33,116.214 h1.52
  text "Signal Layer 2" at 112.742,116.214 h1.52
  text "0.070mm" at 158.45,116.214 h1.52
  text "Dielectric1" at 112.742,113.166 h1.52
  text "FR-4" at 136.612,113.166 h1.52
  text "0.430mm" at 158.45,113.166 h1.52
  text "4.2" at 174.956,113.166 h1.52
  text "4" at 102.33,110.118 h1.52
  text "Bottom Layer" at 112.742,110.118 h1.52
  text "0.070mm" at 158.45,110.118 h1.52
  text "Bottom Solder" at 112.742,107.07 h1.52
  text "Solder Resist" at 136.612,107.07 h1.52
  text "0.010mm" at 158.45,107.07 h1.52
  text "3.5" at 174.956,107.07 h1.52
  text "Bottom Overlay" at 112.742,104.022 h1.52
  text ".Layer_Name" at -5.344,-19.806 h1.52
M13 Component Bodies Top:
  text ".Layer_Name" at -5.344,-19.806 h1.52
M14 Component Bodies Bottom:
  text ".Layer_Name" at -5.344,-19.806 h1.52
M15 Courtyards Top:
  text ".Layer_Name" at -5.344,-19.806 h1.52
M16 Courtyards Bottom:
  text ".Layer_Name" at -5.344,-19.806 h1.52
Drill Drawing:
  circle w0.254: c116.238,82.458 r0.702
  lines w0.254: 115.537,75.441 116.94,75.441 116.94,76.844 115.537,76.844 115.537,75.441 ; 115.537,80.002 116.94,80.002 116.238,78.599 115.537,80.002 ; 115.537,85.265 115.888,85.265 115.888,84.914 116.589,84.914 116.589,85.265 116.94,85.265 116.94,85.967 116.589,85.967 116.589,86.318 115.888,86.318 115.888,85.967 115.537,85.967 115.537,85.265 ; 115.537,88.423 115.888,88.423 116.238,88.072 116.589,88.423 116.94,88.423 116.589,88.774 116.94,89.124 116.589,89.124 116.238,89.475 115.888,89.124 115.537,89.124 115.888,88.774 115.537,88.423
  lines w0.305: 114.264,74.494 196.344,74.494 ; 114.264,90.282 196.344,90.282 ; 122.846,71.336 122.846,93.44 ; 131.279,71.336 131.279,93.44 ; 147.448,71.336 147.448,93.44 ; 154.03,71.336 154.03,93.44 ; 163.559,71.336 163.559,93.44 ; 181.957,71.336 181.957,93.44 ; 114.264,71.336 196.344,71.336 196.344,93.44 114.264,93.44 114.264,71.336
  text "Symbol" at 116.159,91.23 h1.83
  text "Quantity" at 123.793,91.23 h1.83
  text "Finished Hole Size" at 132.226,91.23 h1.83
  text "Plated" at 148.395,91.23 h1.83
  text "Hole Type" at 154.977,91.23 h1.83
  text "Drill Layer Pair" at 164.506,91.23 h1.83
  text "Hole Tolerance" at 182.904,91.23 h1.83
  text "4" at 123.793,88.072 h1.52
  text "173.23mil (4.400mm)" at 132.226,88.072 h1.52
  text "NPTH" at 148.395,88.072 h1.52
  text "Round" at 154.977,88.072 h1.52
  text "Top Layer - Bottom Layer" at 164.506,88.072 h1.52
  text "12" at 123.793,84.914 h1.52
  text "7.87mil (0.200mm)" at 132.226,84.914 h1.52
  text "PTH" at 148.395,84.914 h1.52
  text "Round" at 154.977,84.914 h1.52
  text "Top Layer - Bottom Layer" at 164.506,84.914 h1.52
  text "150" at 123.793,81.756 h1.52
  text "10.00mil (0.254mm)" at 132.226,81.756 h1.52
  text "PTH" at 148.395,81.756 h1.52
  text "Round" at 154.977,81.756 h1.52
  text "Top Layer - Bottom Layer" at 164.506,81.756 h1.52
  text "5" at 123.793,78.599 h1.52
  text "16.00mil (0.406mm)" at 132.226,78.599 h1.52
  text "PTH" at 148.395,78.599 h1.52
  text "Round" at 154.977,78.599 h1.52
  text "Top Layer - Bottom Layer" at 164.506,78.599 h1.52
  text "3" at 123.793,75.441 h1.52
  text "165.35mil (4.200mm)" at 132.226,75.441 h1.52
  text "PTH" at 148.395,75.441 h1.52
  text "Round" at 154.977,75.441 h1.52
  text "Top Layer - Bottom Layer" at 164.506,75.441 h1.52
  text "174 Total" at 123.793,72.283 h1.52
M17 Embedded Cavity:
  text ".Layer_Name" at -5.344,-19.806 h1.52
M18 Embedded Assembly:
  text ".Layer_Name" at -5.344,-19.806 h1.52
M19 Embedded Keepout:
  text ".Layer_Name" at -5.344,-19.806 h1.52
